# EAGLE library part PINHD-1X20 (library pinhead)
PIN HEADER
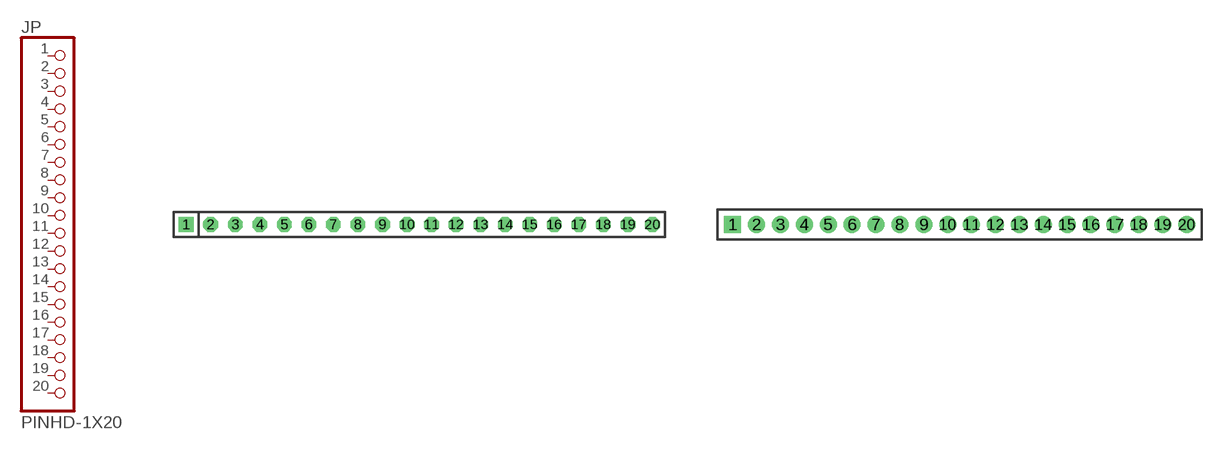
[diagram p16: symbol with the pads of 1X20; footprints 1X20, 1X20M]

Designator prefix JP

## PINHD-1X20  [1X20]
1  1  pas
2  2  pas
3  3  pas
4  4  pas
5  5  pas
6  6  pas
7  7  pas
8  8  pas
9  9  pas
10  10  pas
11  11  pas
12  12  pas
13  13  pas
14  14  pas
15  15  pas
16  16  pas
17  17  pas
18  18  pas
19  19  pas
20  20  pas

## PINHD-1X20M  [1X20M]
Pads as for 1X20

## Footprint 1X20 (pad centres in mm)
PIN HEADER - 0.1"
drill 1.016 square: 1 -24.13,0
drill 1.016 octagon: 2 -21.59,0; 3 -19.05,0; 4 -16.51,0; 5 -13.97,0; 6 -11.43,0; 7 -8.89,0; 8 -6.35,0; 9 -3.81,0; 10 -1.27,0; 11 1.27,0; 12 3.81,0; 13 6.35,0; 14 8.89,0; 15 11.43,0; 16 13.97,0; 17 16.51,0; 18 19.05,0; 19 21.59,0; 20 24.13,0

## Footprint 1X20M (pad centres in mm)
PIN HEADER - 2MM"
drill 0.914 square: 1 -19,0
drill 0.914 round: 2 -17,0; 3 -15,0; 4 -13,0; 5 -11,0; 6 -9,0; 7 -7,0; 8 -5,0; 9 -3,0; 10 -1,0; 11 1,0; 12 3,0; 13 5,0; 14 7,0; 15 9,0; 16 11,0; 17 13,0; 18 15,0; 19 17,0; 20 19,0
